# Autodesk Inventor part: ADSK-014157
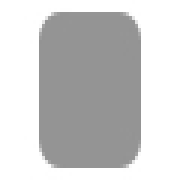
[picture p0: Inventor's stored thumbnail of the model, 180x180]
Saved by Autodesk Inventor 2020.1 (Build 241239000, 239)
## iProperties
Created: 2019-01
Part Number: ADSK-014157
Material: Stahl, weich
Document SubType Name: Modeling
Designer: lutzd
Language: de-DE
Size Designation: 5 x 39,384472 x 39,384472
Categories: <MemberInstance><Categories><Category DisplayName="Sonstige Bauteile" InternalName="5aa15e00-363f-49f2-933f-16f664388e3f" Mnemonic="OTHER"><Category DisplayName
Mass: 60.0398 g
Surface Area: 38.0412 cm^2
Volume: 7.64838 cm^3
Density: 7.85 g/cm^3
Appearance: Halbpoliert
Dimensions: 39,4x39,4x5 mm
Mass: 0,06 kg
DocNumber: ADSK-014157
Folder: 01 - Themengebiete\Simplification\01 - Packaging machine\
VDS_Category: 3D Komponenten
VDS_NumSchm: Autodesk
IsCustomPart: 1
Title: end cap
Author: lutzd
Revision Number: -
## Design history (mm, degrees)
sketch "Sketch1"
  geometry: L1 (0, 20.175)-(0, -21.446); L2 (-20.203, 0)-(20.169, 0); L3 (-19.692, 19.692)-(19.692, 19.692); L4 (19.692, 19.692)-(19.692, -19.692); L5 (19.692, -19.692)-(-19.692, -19.692); L6 (-19.692, -19.692)-(-19.692, 19.692); 1 further point
  constraints: 12 end point, 2 horizontal, 2 parallel, 2 point on line, 1 perpendicular, 1 vertical
  dimensions: "d0" = 39.38447 distance between parallel lines of L5 L3 (= height); "d1" = 19.69224 distance between parallel lines of L2 L3 (= 0.5 x height); "d2" = 39.38447 distance between parallel lines of L6 L4 (= width); "d3" = 19.69224 distance between parallel lines of L6 L1 (= 0.5 x width)
extrude "Extrusion1" new body sketch "Sketch1" distance "d4" = 5 (= thickness); taper "d5" = 0 deg
fillet "Fillet1" dims "d6" = 5 (= fillet), "d7" = 0, "fillet" = 5 [user parameter; used in 1 equation term]
chamfer "Chamfer1" distance "d8" = 0 (computed from chamfer); stored, may be unused: second distance "d9" = 2, angle "d10" = 45 deg; dims "d11" = 0, "chamfer" = 0 [user parameter; used in 1 equation term]
body "Solid1"
other parameters: "thickness" = 5 [user parameter; used in 1 equation term], "width" = 39.38447 [user parameter; used in 2 equation terms], "height" = 39.38447 [user parameter; used in 2 equation terms]
